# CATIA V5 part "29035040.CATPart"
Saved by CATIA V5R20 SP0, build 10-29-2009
Part number: 29035040
Definition: NONE
Nomenclature: 29035040
Source: Unknown
Description: 29035040
Bounding box of the stored display mesh (mm): x -20 to 44.548, y -31.5 to 66.048, z -21.5 to 21.5
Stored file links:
  C:\Users\Utente\Desktop\IO LAVORO\3D X SITO CF\X SITO\PLASTICA\RF1\29035040.CATPart
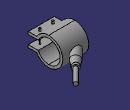
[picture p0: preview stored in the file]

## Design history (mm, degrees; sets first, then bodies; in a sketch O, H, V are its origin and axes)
Body1 "29035040" (main body)
  Solid1: solid without history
